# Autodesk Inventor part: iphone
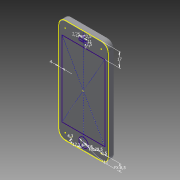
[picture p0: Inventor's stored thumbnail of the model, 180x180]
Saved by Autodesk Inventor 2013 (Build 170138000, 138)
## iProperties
Created: 2013-03
Part Number: iphone
Material: Generic
Document SubType Name: Modeling
Designer: md
Density: 1 g/cm^3
d3: 124,000 mm
d22: 59,000 mm
d24: 124,000 mm
d25: 8,000 mm
d26: 8,000 mm
d27: 8,000 mm
d28: 7,700 mm
d29: 0.00 deg
d30: 17,000 mm
d31: 4,000 mm
d33: 8,500 mm
d34: 29,500 mm
d35: 11,000 mm
d36: 2,500 mm
d37: 5,000 mm
d38: 2,500 mm
d39: 2,750 mm
d40: 9,500 mm
d41: 3,400 mm
d42: 0,500 mm
d43: 4,300 mm
d44: 12,000 mm
d49: 1,000 mm
Grundkoerper_Breite: 59,000 mm
Grundkoerper_Hoehe: 124,000 mm
Grundkoerper_Dicke: 7,700 mm
Grundkoerper_Rundung_Radius: 8,000 mm
Homebutton_Durchmesser: 11,000 mm
Author: md
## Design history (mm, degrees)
sketch "Sketch1"
  geometry: L1 (-21.467, -62.022)-(21.533, -62.022); L2 (29.533, -54.022)-(29.533, 53.978); L3 (21.533, 61.978)-(-21.467, 61.978); L4 (-29.467, 53.978)-(-29.467, -54.022); L5 (-29.467, -62.022)-(29.533, 61.978); L6 (29.533, -62.022)-(-29.467, 61.978); A1 r 8 centre (-21.467, 53.978) between (-21.467, 61.978) and (-29.467, 53.978); A2 r 8 centre (21.533, 53.978) between (29.533, 53.978) and (21.533, 61.978); A3 r 8 centre (21.533, -54.022) between (21.533, -62.022) and (29.533, -54.022); A4 r 8 centre (-21.467, -54.022) between (-29.467, -54.022) and (-21.467, -62.022); 2 further points
  constraints: 12 end point, 8 point on circle, 8 point on line, 8 tangent, 4 centre point, 3 midpoint, 2 parallel, 1 equal radius, 1 horizontal, 1 perpendicular
  dimensions: "d22" = 59 distance of L5.end L6.end (= Grundkoerper_Breite); "d24" = 124 distance of L6.end L5.start (= Grundkoerper_Hoehe); "d25" = 8 radius of A1 (= Grundkoerper_Rundung_Radius); "d26" = 8 radius of A2 (= Grundkoerper_Rundung_Radius); "d27" = 8 radius of A3
extrude "Grundkoerper" new body sketch "Sketch1" distance "d28" = 7.7 (= Grundkoerper_Dicke); taper "d29" = 0 deg
sketch "Vorderseite"
  geometry: L1 (29.467, 53.978)-(29.467, -54.022) reference; L2 (-21.533, 61.978)-(21.467, 61.978) reference; L3 (-29.533, -54.022)-(-29.533, 53.978) reference; L4 (21.467, -62.022)-(-21.533, -62.022) reference; L5 (29.467, 53.978)-(29.467, -54.022) reference; L6 (-21.533, 61.978)-(21.467, 61.978) reference; L7 (-29.533, -54.022)-(-29.533, 53.978) reference; L8 (21.467, -62.022)-(-21.533, -62.022) reference; L9 (-25.533, -44.978)-(25.533, -44.978); L10 (25.533, -44.978)-(25.533, 44.978); L11 (25.533, 44.978)-(-25.533, 44.978); L12 (-25.533, 44.978)-(-25.533, -44.978); L13 (-25.533, -44.978)-(25.533, 44.978); L14 (25.533, -44.978)-(-25.533, 44.978); L15 (-5.533, 49.978)-(5.467, 49.978); L16 (5.467, 49.978)-(5.467, 52.478); L17 (5.467, 52.478)-(-5.533, 52.478); L18 (-5.533, 52.478)-(-5.533, 49.978); L19 (-5.533, 49.978)-(5.467, 52.478); L20 (5.467, 49.978)-(-5.533, 52.478); L21 (-0.033, 61.978)-(-0.033, -62.022); C1 r 5.5 at (-0.033, -53.522); C2 r 1.25 at (-0.033, 56.478); A1 r 8 centre (21.467, 53.978) between (29.467, 53.978) and (21.467, 61.978) reference; A2 r 8 centre (-21.533, 53.978) between (-21.533, 61.978) and (-29.533, 53.978) reference; A3 r 8 centre (-21.533, -54.022) between (-29.533, -54.022) and (-21.533, -62.022) reference; A4 r 8 centre (21.467, -54.022) between (21.467, -62.022) and (29.467, -54.022) reference; A5 r 8 centre (21.467, 53.978) between (29.467, 53.978) and (21.467, 61.978) reference; A6 r 8 centre (-21.533, 53.978) between (-21.533, 61.978) and (-29.533, 53.978) reference; A7 r 8 centre (-21.533, -54.022) between (-29.533, -54.022) and (-21.533, -62.022) reference; A8 r 8 centre (21.467, -54.022) between (21.467, -62.022) and (29.467, -54.022) reference; 3 further points
  constraints: 26 end point, 7 midpoint, 4 parallel, 2 centre point, 2 horizontal, 2 perpendicular, 2 point on line
  dimensions: "d30" = 17 distance between parallel lines of L2 L11; "d31" = 4 distance between parallel lines of L12 L3; "Homebutton_Durchmesser" = 11 diameter of C1; "d33" = 8.5 distance from line of L4 C1.centre (= 0.5 x d30); "d34" = 29.5 distance from line of C1.centre L1 (= 0.5 x Grundkoerper_Breite); "d35" = 11 distance of L16.end L17.end; "d36" = 2.5 distance of L15.end L16.end; "d37" = 5 distance between parallel lines of L11 L15; "d38" = 2.5 diameter of C2; "d39" = 2.75 distance edge to line of C2 L17
  node "Projected Loop1"
sketch "Unterseite"
  geometry: L1 (43, 0)-(43, 7.7) reference; L2 (0, 7.7)-(43, 7.7) reference; L3 (0, 0)-(0, 7.7) reference; L4 (21.467, 0)-(21.5, 7.7); L5 (0, 3.85)-(43, 3.85); L6 (17.25, 2.15)-(25.75, 2.15); L7 (26.25, 2.65)-(26.25, 5.05); L8 (25.75, 5.55)-(17.25, 5.55); L9 (16.75, 5.05)-(16.75, 2.65); L10 (16.75, 2.15)-(26.25, 5.55); L11 (26.25, 2.15)-(16.75, 5.55); C1 r 2.15 at (40.4, 3.85); A1 r 0.5 centre (17.25, 5.05) between (17.25, 5.55) and (16.75, 5.05); A2 r 0.5 centre (25.75, 5.05) between (26.25, 5.05) and (25.75, 5.55); A3 r 0.5 centre (25.75, 2.65) between (25.75, 2.15) and (26.25, 2.65); A4 r 0.5 centre (17.25, 2.65) between (16.75, 2.65) and (17.25, 2.15); 1 further point
  constraints: 16 end point, 9 point on line, 8 point on circle, 8 tangent, 6 midpoint, 5 centre point, 3 equal radius, 2 parallel, 1 horizontal, 1 perpendicular
  dimensions: "d40" = 9.5 distance of L11.end L10.end; "d41" = 3.4 distance of L10.end L11.start; "d42" = 0.5 radius of A1; "d43" = 4.3 diameter of C1; "d44" = 12 distance edge to line of C1 L7
chamfer "Chamfer1" distance "d49" = 1; stored, may be unused: second distance "d50" = 2, angle "d51" = 45 deg
body "Solid1"
other parameters: "Grundkoerper_Breite" = 59 [user parameter; used in 2 equation terms], "Grundkoerper_Hoehe" = 124 [user parameter; used in 2 equation terms], "Grundkoerper_Dicke" = 7.7 [user parameter; used in 1 equation term], "d3" = 124 (= Grundkoerper_Hoehe), "Grundkoerper_Rundung_Radius" = 8 [user parameter; used in 2 equation terms], "Freistellung" = 1 [user parameter]
